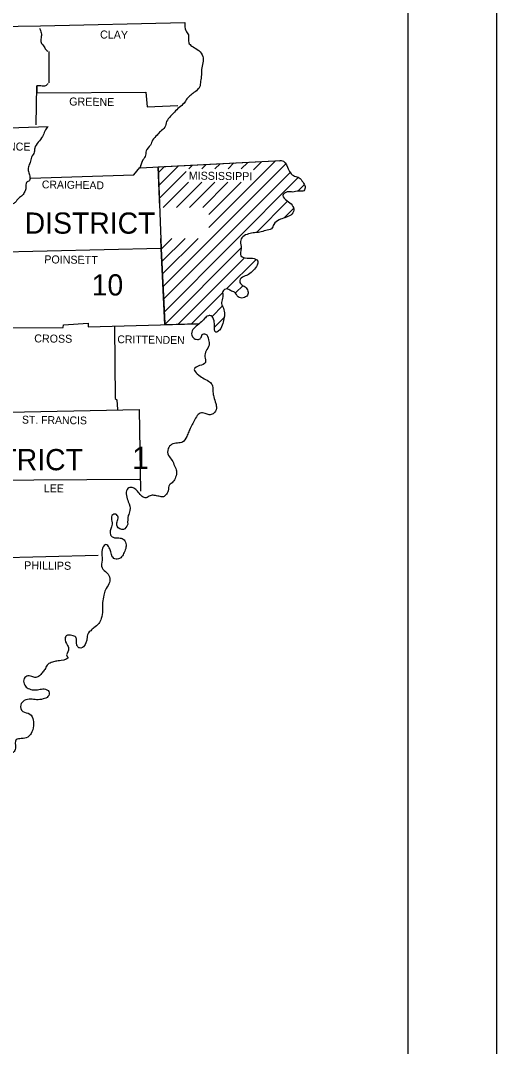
# Model space of a CAD drawing. Extents: x 1366406 to 1373462, y 376856 to 381998.
# Drawn here: x 1370769 to 1371025, y 380444 to 380996 of the extents above; entities that cross this region are included whole.
import ezdxf

# ---------------------------------------------------------------- set-up
doc = ezdxf.new("R2010")
doc.units = 0
for name, color, linetype in [('R_Border', 7, 'Continuous'), ('R_Draft', 7, 'Continuous'), ('R_No Plot', 7, 'Continuous')]:
    doc.layers.add(name, color=color, linetype=linetype)

msp = doc.modelspace()

# ---------------------------------------------------------------- linework, layer by layer
at = {"layer": 'R_Border'}
msp.add_line((1370977.66, 379179.32), (1370977.66, 381233.92), dxfattribs=at)
at = {"layer": 'R_Draft'}
for p, q in [((1370833.56, 380916.5), (1370834.76, 380920.2)), ((1370833.86, 380917.7), (1370835.06, 380920.6))]:
    msp.add_line(p, q, dxfattribs=at)
for points in [[(1370308.96, 380990), (1370470.66, 380989.9), (1370612.56, 380990.2), (1370779.96, 380992.8), (1370857.56, 380994.6)], [(1370784.36, 380979), (1370784.36, 380962.1)], [(1370777.56, 380939.6), (1370778.06, 380960.5), (1370778.06, 380956.8), (1370836.56, 380957.1), (1370837.36, 380949.3), (1370853.86, 380949.9)], [(1370746.96, 380937.4), (1370784.06, 380938.7)], [(1370833.56, 380916.5), (1370909.46, 380920.4)], [(1370843.16, 380917), (1370909.46, 380920.4)], [(1370845.86, 380852.7), (1370911.66, 380918.5), (1370911.76, 380918.6)], [(1370866.66, 380915.9), (1370869.06, 380918.3)], [(1370870.46, 380884.4), (1370906.26, 380920.2)], [(1370873.76, 380915.9), (1370876.56, 380918.7)], [(1370880.86, 380915.9), (1370883.96, 380919.1)], [(1370887.86, 380915.9), (1370891.36, 380919.4)], [(1370894.56, 380915.5), (1370898.86, 380919.8)], [(1370774.56, 380911), (1370830.06, 380912.8), (1370833.36, 380916.6)], [(1370844.06, 380895.2), (1370843.16, 380917)], [(1370843.16, 380916.4), (1370844.86, 380873.1), (1370846.86, 380832.8)], [(1370843.26, 380913.8), (1370846.66, 380917.2)], [(1370843.56, 380907), (1370854.16, 380917.5)], [(1370843.86, 380900.2), (1370858.26, 380914.6)], [(1370846.16, 380845.9), (1370914.26, 380914)], [(1370859.66, 380915.9), (1370861.66, 380917.9)], [(1370845.96, 380895.2), (1370859.56, 380908.8)], [(1370846.56, 380839.2), (1370918.66, 380911.4)], [(1370853.06, 380895.2), (1370866.66, 380908.8)], [(1370860.16, 380895.2), (1370873.76, 380908.8)], [(1370867.16, 380895.2), (1370880.76, 380908.8)], [(1370870.46, 380891.4), (1370887.86, 380908.8)], [(1370918.36, 380903.9), (1370921.76, 380907.4)], [(1370896.16, 380881.7), (1370912.86, 380898.5)], [(1370911.06, 380889.6), (1370916.06, 380894.6)], [(1370846.86, 380832.2), (1370844.86, 380873.1), (1370844.66, 380878.6)], [(1370844.96, 380873), (1370850.56, 380878.6)], [(1370845.26, 380866.2), (1370857.66, 380878.6)], [(1370845.56, 380859.5), (1370864.66, 380878.6)], [(1370844.86, 380873.1), (1370752.76, 380871)], [(1370846.86, 380832.4), (1370887.76, 380873.4)], [(1370853.86, 380832.4), (1370889.66, 380868.2)], [(1370880.06, 380851.5), (1370895.86, 380867.3)], [(1370884.86, 380849.3), (1370888.96, 380853.3)], [(1370861.16, 380832.6), (1370878.06, 380849.5)], [(1370872.26, 380836.6), (1370877.86, 380842.3)], [(1370873.46, 380830.8), (1370878.76, 380836)], [(1370753.56, 380830.5), (1370792.16, 380830.7), (1370792.26, 380832.1), (1370805.66, 380833.1), (1370805.66, 380831), (1370863.86, 380832.6)], [(1370819.66, 380831), (1370820.16, 380792.5), (1370821.06, 380791.9), (1370821.36, 380786.7)], [(1370819.66, 380831), (1370820.16, 380792.5), (1370821.06, 380791.9), (1370821.36, 380786.7)], [(1370819.66, 380831), (1370820.16, 380792.5), (1370821.06, 380791.9), (1370821.36, 380786.7)], [(1370819.66, 380831), (1370820.16, 380792.5), (1370821.06, 380791.9), (1370821.36, 380786.7)], [(1370819.66, 380831), (1370820.16, 380792.5), (1370821.06, 380791.9), (1370821.36, 380786.7)], [(1370865.16, 380832.6), (1370846.86, 380832.2)], [(1370753.56, 380785), (1370832.96, 380786.6)], [(1370832.96, 380786.6), (1370833.76, 380742.8)], [(1370832.96, 380786.6), (1370833.76, 380742.8)], [(1370832.96, 380786.6), (1370833.76, 380742.8)], [(1370832.96, 380786.6), (1370833.76, 380742.8)], [(1370832.96, 380786.6), (1370833.76, 380742.8)], [(1370832.96, 380786.6), (1370833.76, 380742.8)], [(1370832.96, 380786.6), (1370833.76, 380742.8)], [(1370832.96, 380786.6), (1370833.76, 380742.8)], [(1370753.56, 380660), (1370761.36, 380660.5), (1370761.26, 380680.8), (1370753.96, 380681.3), (1370754.36, 380721), (1370748.06, 380721.9), (1370747.86, 380748.6), (1370833.16, 380749.2)], [(1370754.56, 380706.9), (1370810.96, 380708.3)]]:
    msp.add_lwpolyline(points, dxfattribs=at)
for points in [[(1370779.46, 380991.5), (1370780.36, 380989), (1370780.26, 380986.3), (1370780.26, 380983.8), (1370781.56, 380982.1), (1370782.86, 380980), (1370783.86, 380979.1)], [(1370857.56, 380994.6), (1370858.06, 380990.2), (1370859.46, 380987.9), (1370859.66, 380983.7), (1370861.36, 380981.9), (1370864.26, 380980.1), (1370866.86, 380977.2), (1370867.46, 380973.8), (1370866.66, 380970.3), (1370866.46, 380966.4), (1370866.06, 380963), (1370865.46, 380959.9), (1370863.06, 380957.4), (1370860.76, 380955.6), (1370858.66, 380953.5), (1370857.16, 380951.3), (1370854.56, 380948.9), (1370851.96, 380946.4), (1370849.86, 380944.2), (1370847.76, 380941.4), (1370846.76, 380938.3), (1370844.46, 380936.1), (1370842.66, 380934.1), (1370840.26, 380931.4), (1370839.06, 380928.7), (1370836.76, 380925.6), (1370836.26, 380922.6), (1370834.76, 380920.2), (1370834.66, 380919.8)], [(1370783.96, 380961.8), (1370782.66, 380960.5), (1370780.16, 380960.5), (1370778.06, 380960.5)], [(1370783.76, 380938.6), (1370782.26, 380936.2), (1370781.06, 380933.4), (1370778.66, 380930.2), (1370776.86, 380927.1), (1370776.56, 380925), (1370775.16, 380922.2), (1370774.36, 380919.4), (1370773.46, 380917), (1370773.46, 380914.5), (1370774.16, 380912), (1370773.96, 380909.7), (1370772.46, 380908.6), (1370772.06, 380905.7), (1370771.46, 380903.7), (1370770.16, 380901.7), (1370768.26, 380900.2), (1370766.26, 380897.9), (1370764.76, 380896.9)], [(1370908.36, 380920.3), (1370909.46, 380920.4), (1370912.86, 380916.8), (1370914.36, 380913.8), (1370916.56, 380912.1), (1370919.06, 380911.2), (1370920.96, 380908.9), (1370922.26, 380906.4), (1370921.56, 380904.2), (1370918.76, 380904), (1370915.66, 380903.5), (1370912.66, 380903.6), (1370910.26, 380901.6), (1370912.46, 380898.9), (1370915.36, 380896.4), (1370916.16, 380893.7), (1370914.56, 380891.1), (1370911.36, 380889.7), (1370908.26, 380888.5), (1370905.46, 380886.1), (1370904.16, 380883.8), (1370901.06, 380882.8), (1370897.86, 380881.9), (1370895.06, 380881.6), (1370891.86, 380881), (1370888.76, 380879.5), (1370887.46, 380876.9), (1370887.86, 380873.2), (1370887.76, 380869.3), (1370891.06, 380868), (1370893.96, 380867.9), (1370896.76, 380866.4), (1370896.46, 380864.2), (1370894.36, 380861.4), (1370891.86, 380859.2), (1370889.36, 380858.1), (1370887.06, 380856), (1370887.86, 380853.9), (1370889.96, 380852.5), (1370891.46, 380850.2), (1370891.26, 380848.1), (1370888.86, 380846.6), (1370886.26, 380847.2), (1370884.36, 380849.7), (1370882.16, 380850.5), (1370880.26, 380851.4), (1370878.06, 380850.1), (1370878.06, 380847.2), (1370877.26, 380844.1), (1370877.96, 380841.8), (1370878.86, 380838.6), (1370878.76, 380836.2), (1370877.96, 380832.8), (1370876.26, 380829.3), (1370874.26, 380828.2), (1370873.46, 380832), (1370873.06, 380835.1), (1370871.86, 380836.9), (1370870.26, 380837), (1370868.16, 380835.5), (1370865.86, 380833.2), (1370862.96, 380830.7), (1370861.26, 380828.2), (1370862.16, 380825.1), (1370864.36, 380824.3), (1370866.06, 380824.9), (1370866.96, 380826.9), (1370868.66, 380827.2), (1370870.26, 380824.1)], [(1370908.36, 380920.3), (1370909.46, 380920.4), (1370912.86, 380916.8), (1370914.36, 380913.8), (1370916.56, 380912.1), (1370919.06, 380911.2), (1370920.96, 380908.9), (1370922.26, 380906.4), (1370921.56, 380904.2), (1370918.76, 380904), (1370915.66, 380903.5), (1370912.66, 380903.6), (1370910.26, 380901.6), (1370912.46, 380898.9), (1370915.36, 380896.4), (1370916.16, 380893.7), (1370914.56, 380891.1), (1370911.36, 380889.7), (1370908.26, 380888.5), (1370905.46, 380886.1), (1370904.16, 380883.8), (1370901.06, 380882.8), (1370897.86, 380881.9), (1370895.06, 380881.6), (1370891.86, 380881), (1370888.76, 380879.5), (1370887.46, 380876.9), (1370887.86, 380873.2), (1370887.76, 380869.3), (1370891.06, 380868), (1370893.96, 380867.9), (1370896.76, 380866.4), (1370896.46, 380864.2), (1370894.36, 380861.4), (1370891.86, 380859.2), (1370889.36, 380858.1), (1370887.06, 380856), (1370887.86, 380853.9), (1370889.96, 380852.5), (1370891.46, 380850.2), (1370891.26, 380848.1), (1370888.86, 380846.6), (1370886.26, 380847.2), (1370884.36, 380849.7), (1370882.16, 380850.5), (1370880.26, 380851.4), (1370878.06, 380850.1), (1370878.06, 380847.2), (1370877.26, 380844.1), (1370877.96, 380841.8), (1370878.86, 380838.6), (1370878.76, 380836.2), (1370877.96, 380832.8), (1370876.26, 380829.3), (1370874.26, 380828.2), (1370873.46, 380832), (1370873.06, 380835.1), (1370871.86, 380836.9), (1370870.26, 380837), (1370868.16, 380835.5), (1370865.86, 380833.2), (1370865.26, 380832.7)], [(1370870.26, 380824.1), (1370870.66, 380821.2), (1370868.96, 380818.1), (1370868.36, 380815), (1370868.66, 380811.9), (1370865.46, 380810.2), (1370862.66, 380808.2), (1370864.26, 380805.8), (1370867.26, 380803.6), (1370870.26, 380801.9), (1370872.16, 380800.2), (1370872.66, 380796.1), (1370873.16, 380793.5), (1370874.16, 380789.9), (1370874.56, 380787.4), (1370872.76, 380784.4), (1370870.66, 380783.8), (1370868.46, 380784.5), (1370865.86, 380784.7), (1370863.76, 380782.7), (1370862.26, 380779.9), (1370860.76, 380777.1), (1370859.66, 380774.7), (1370858.56, 380772.1), (1370856.36, 380769.1), (1370853.66, 380768.6), (1370850.46, 380767.8), (1370848.56, 380765.6), (1370848.86, 380761.9), (1370850.66, 380759.4), (1370852.06, 380756.3), (1370853.06, 380753.6), (1370852.56, 380750.2), (1370851.16, 380747.7), (1370849.36, 380746.2), (1370848.56, 380743), (1370847.26, 380740.6), (1370846.06, 380739.8), (1370843.66, 380740), (1370841.06, 380740.5), (1370838.86, 380740.3), (1370836.76, 380739.2), (1370834.66, 380739.9), (1370832.46, 380742.3), (1370830.66, 380744.1), (1370828.66, 380744.8), (1370826.56, 380743.7), (1370826.16, 380740.4), (1370827.16, 380737), (1370828.06, 380732.4), (1370827.16, 380729.6), (1370826.86, 380725)], [(1370826.86, 380725), (1370824.56, 380722.1), (1370821.16, 380723.9), (1370821.16, 380726.3), (1370821.66, 380728.8), (1370820.46, 380730.4), (1370818.36, 380729.7), (1370818.36, 380726.6), (1370818.16, 380723.6), (1370817.56, 380719.3), (1370818.96, 380718), (1370822.16, 380717.6), (1370824.46, 380717), (1370825.86, 380714.7), (1370825.76, 380711.9), (1370824.66, 380709.2), (1370823.06, 380707), (1370820.56, 380706.2), (1370818.56, 380707.5), (1370817.76, 380710.1), (1370816.86, 380712.4), (1370815.16, 380714.1), (1370813.36, 380712.2), (1370812.96, 380708.7), (1370813.06, 380705.7), (1370813.06, 380701.6), (1370815.66, 380698.9), (1370817.26, 380695.8), (1370816.76, 380693), (1370814.86, 380689.7), (1370814.06, 380686.8), (1370813.26, 380682.9), (1370813.36, 380678.6), (1370812.66, 380674.4), (1370811.26, 380671.6), (1370808.66, 380669.3), (1370806.96, 380667.8), (1370805.56, 380666.3), (1370804.86, 380663.3), (1370804.36, 380661.2), (1370802.46, 380658.7), (1370800.96, 380658.5), (1370799.76, 380659.5), (1370799.36, 380661.2), (1370799.36, 380662.9), (1370798.56, 380664.6), (1370796.06, 380665.3), (1370794.06, 380665.2), (1370793.16, 380663.8), (1370794.46, 380659.9), (1370794.96, 380657.4), (1370794.26, 380654), (1370794.66, 380653.6), (1370791.06, 380651.7), (1370788.16, 380651.4), (1370785.76, 380650.7), (1370783.46, 380649.2), (1370782.36, 380647), (1370780.76, 380645.2), (1370779.36, 380643.5), (1370777.46, 380642.7), (1370775.36, 380643.1), (1370772.56, 380643.4), (1370770.96, 380641.4), (1370771.46, 380638.5), (1370773.36, 380636.8), (1370776.16, 380636), (1370779.06, 380636.2), (1370781.86, 380636.5), (1370784.46, 380635.1), (1370783.96, 380632.4), (1370781.46, 380631.1), (1370777.76, 380630.7), (1370774.76, 380631), (1370771.16, 380630.2), (1370769.36, 380627.9), (1370770.36, 380624.4), (1370774.26, 380623), (1370776.06, 380619.7), (1370776.16, 380616.6), (1370774.86, 380612.5), (1370773.06, 380610.6), (1370769.56, 380609.8), (1370766.86, 380609.3), (1370766.46, 380604.7), (1370765.26, 380602.4), (1370763.16, 380601.7), (1370760.16, 380603.2), (1370758.36, 380603.9), (1370756.16, 380604.9), (1370753.36, 380606.6), (1370751.26, 380606.3), (1370751.86, 380601.9), (1370752.06, 380601.7), (1370754.46, 380598.4), (1370756.86, 380595.8), (1370757.96, 380592.7)]]:
    msp.add_spline(points, degree=3, dxfattribs=at)
at = {"layer": 'R_No Plot'}
msp.add_lwpolyline([(1367691.79, 381272.86), (1371025.18, 381272.86), (1371025.18, 379139.49), (1367691.79, 379139.49)], close=True, dxfattribs=at)

# ---------------------------------------------------------------- texts
at = {"layer": 'R_Draft'}
for s, height, rotation, p in [('CLAY', 4.299, 359.2258, (1370811.96, 380986)), ('GREENE', 4.301, 359.2361, (1370795.36, 380950)), ('LAWRENCE', 4.301, 359.2678, (1370741.96, 380926.1)), ('MISSISSIPPI', 4.2995, 359.3097, (1370859.66, 380910.2)), ('CRAIGHEAD', 4.201, 359.1159, (1370780.66, 380905.5)), ('POINSETT', 4.3, 359.1987, (1370781.96, 380865.2)), ('CROSS', 4.3, 359.3839, (1370776.56, 380822.7)), ('CRITTENDEN', 4.201, 359.213, (1370821.26, 380822.3)), ('ST. FRANCIS', 4.1993, 359.2216, (1370769.96, 380779.1)), ('LEE', 4.301, 359.4327, (1370781.66, 380742.2)), ('PHILLIPS', 4.3, 359.3179, (1370771.16, 380700.8))]:
    msp.add_text(s, height=height, rotation=rotation, dxfattribs=at).set_placement(p)
for s, height, p in [('DISTRICT', 11.4, (1370771.46, 380881.1)), ('10', 11.4, (1370807.48, 380847.9)), ('DISTRICT', 11.4, (1370732.46, 380754)), ('1', 12, (1370829.26, 380754.7))]:
    msp.add_text(s, height=height, dxfattribs=at).set_placement(p)

doc.saveas('drawing.dxf')
